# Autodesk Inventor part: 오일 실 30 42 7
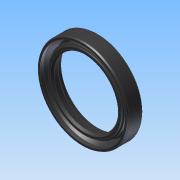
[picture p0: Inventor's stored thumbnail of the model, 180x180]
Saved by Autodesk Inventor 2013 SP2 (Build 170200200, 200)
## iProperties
Created: 2025-06
Part Number: 오일 실 30 42 7
Material: Generic
Document SubType Name: Modeling
Designer: a
Density: 1 g/cm^3
Author: a
변환 표준: STEP AP214IS
전처리기: Build: 200, Release: 2013 SP2 Update 6 - Date: Thu 07/17/2014
전송 단위: 밀리미터
불확실성: 0.01
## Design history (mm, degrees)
node "오일 실 30 42 71"
body "Solid1"
node "기준1"
